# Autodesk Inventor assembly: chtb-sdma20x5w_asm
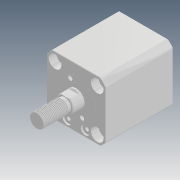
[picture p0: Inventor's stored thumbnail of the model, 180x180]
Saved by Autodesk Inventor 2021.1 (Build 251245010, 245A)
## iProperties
Company: Microsoft
Created: 2018-05
Part Number: chtb-sdma20x5w_asm
Description: STEP AP214
Document SubType Name: Assembly
Designer: user
Title: chtb-sdma20x5w_asm.STEP
Author: Windows
Revision Number: ÈÎºÎ
Sending System: SolidWorks 2015
Preprocessor: SwSTEP 2.0
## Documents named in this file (4)
- D:\Vault_2016\Projekty\Clamptek\Hydraulic\CHTB\CHTB-20\Inventor\CHTB-SDMA20x5W\chtb-sdma20x5w_asm.iam
- D:\Vault_2016\Projekty\Clamptek\Hydraulic\CHTB\CHTB-20\Inventor\CHTB-SDMA20x5W\CHTB-SDMA20X5NBT.ipt
- D:\Vault_2016\Projekty\Clamptek\Hydraulic\CHTB\CHTB-20\Inventor\CHTB-SDMA20x5W\CHTB-SDMA20X5WHSG.ipt
- D:\Vault_2016\Projekty\Clamptek\Hydraulic\CHTB\CHTB-20\Inventor\CHTB-SDMA20x5W\QG_3.ipt
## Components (3 placed, 3 different names)
1. CHTB-SDMA20X5NBT_1
2. CHTB-SDMA20X5WHSG_2
3. QG_3_3
